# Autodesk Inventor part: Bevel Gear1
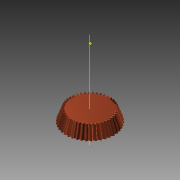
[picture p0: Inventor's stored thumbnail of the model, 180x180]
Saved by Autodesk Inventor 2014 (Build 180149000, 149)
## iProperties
Created: 2008-07
Part Number: Bevel Gear1
Material: Steel, Mild
Document SubType Name: Modeling
Designer: tangg
Categories: <?xml version="1.0" encoding="UTF-16"?> <MemberInstance><Categories><FamilyTemplate><FamilyTemplateParameter ValueType="xs:double" Id="1" ObjectReferenceKey="da
Mass: 60.9118 g
Surface Area: 34.3074 cm^2
Volume: 7.7496 cm^3
Density: 7.86 g/cm^3
Appearance: Copper - Polished
CustomPartVersion: 1
Author: tangg
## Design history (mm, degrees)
node "Top Point"
node "Mesh Plane2"
sketch "Teeth Body Sketch"
  geometry: L1 (0, 0)-(13.905, -43.186); L2 (13.905, -43.186)-(15.362, -42.687); L3 (15.362, -42.687)-(0, 0); L4 (14.7, -42.914)-(0, 0); L5 (11.453, -35.569)-(12.653, -35.158); L6 (13.905, -43.186)-(11.453, -35.569); L7 (15.362, -42.687)-(12.653, -35.158); L8 (0, -51.823)-(0, 8.637) reference; L9 (0, -42.914)-(15.362, -42.914)
  constraints: 16 end point, 4 point on line, 3 perpendicular, 2 collinear, 1 horizontal alignment, 1 vertical alignment
  dimensions: "d0" = 29.4 diameter of L4.start L8 (= da_de); "d1" = 27.81066 diameter of L1.end L8 (= da_dfe); "d2" = 30.72445 diameter of L2.end L8 (= da_dae); "d3" = 8 distance between parallel lines of L2 L5 (= da_b); "d4" = 42.68672 vertical distance of L2.end L1.start (= da_ve)
revolve "Teeth Body" sketch "Teeth Body Sketch" stored, may be unused: angle "d5" = 90 deg
node "Start Point"
node "Tooth Plane"
sketch "Start Sketch"
  geometry: L1 (0, -35.958)-(0, 11.125) reference; L2 (-0.217, -0.185)-(0.217, -0.185); A1 r 5.975 centre (-6.038, -1.531) between (-0.217, -0.185) and (-1.189, 1.96); A2 r 5.975 centre (6.038, -1.531) between (1.189, 1.96) and (0.217, -0.185); A3 r 16.701 centre (0, -14.699) between (1.189, 1.96) and (-1.189, 1.96); 1 further point
  constraints: 6 point on circle, 3 centre point, 3 symmetric about line, 2 end point, 1 coincident, 1 perpendicular, 1 other
  dimensions: "d7" = 5.97468 radius of A1 (= fd_rr); "d8" = 6.03788 horizontal distance of point (0, -14.699) A1.centre (= fd_x); "d9" = 13.16739 vertical distance of point (0, -14.699) A1.centre (= fd_y); "d57" = 16.70053 radius of A3 (= 0.5 x fd_dva + 0.3 x da_he); "d58" = 14.51373 distance from line of A3.centre L2 (= 0.5 x fd_dva - 1.12 x da_he)
node "End Point"
  node "End Plane"
sketch "3D Sketch Right"
  node "Helical Curve Right" dims "d65" = 286.15708 (computed from da_dm, da_delta, da_beta), "d66" = 31.5, "d67" = 29.4 (= da_de), "d68" = -3.30022 (= -da_delta), "d69" = 7.64113 (computed from fd_loft, da_delta)
node "End Plane Right"
sketch "End Sketch Right"
  geometry: L1 (0, -17.689)-(0, 5.893) reference; L2 (-0.178, -0.828)-(0.178, -0.828); A1 r 4.917 centre (-4.969, -1.936) between (-0.178, -0.828) and (-0.978, 0.937); A2 r 4.917 centre (4.969, -1.936) between (0.978, 0.937) and (0.178, -0.828); A3 r 13.744 centre (0, -12.772) between (0.978, 0.937) and (-0.978, 0.937); 1 further point
  constraints: 6 point on circle, 3 centre point, 3 symmetric about line, 2 end point, 1 coincident, 1 perpendicular, 1 other
  dimensions: "d70" = 4.96882 horizontal distance of A3.centre A1.centre (computed from fd_x, fd_ratio); "d71" = 10.83599 vertical distance of point (0, -12.772) A1.centre (computed from fd_y, fd_ratio); "d72" = 4.91681 radius of A1 (computed from fd_rr, fd_ratio); "d73" = 11.94395 distance from line of point (0, -12.772) L2 (computed from d58, fd_ratio); "d74" = 13.74356 radius of A3 (computed from d57, fd_ratio)
feature "Loft Right" sketch "End Sketch Right" dims "d75" = 0, "d76" = 90 deg, "d77" = 0, "d78" = 90 deg, "d79" = 0, "d80" = 90 deg, "d85" = 20, "da_teethtype" = 0 [user parameter]
sketch "3D Sketch Left"
  node "Helical Curve Left" dims "d26" = 286.15708 (computed from da_dm, da_delta, da_beta), "d27" = 7.64113 (computed from fd_loft, da_delta), "d28" = 29.4 (= da_de), "d29" = -3.30022 (= -da_delta)
node "End Plane Left"
sketch "End Sketch Left" dims "d56" = 11.97023 (derived)
  geometry: L1 (0, -33.711)-(0, 11.326) reference; L2 (-0.178, -0.827)-(0.178, -0.827); A1 r 4.917 centre (-4.969, -1.935) between (-0.178, -0.827) and (-0.978, 0.938); A2 r 4.917 centre (4.969, -1.935) between (0.978, 0.938) and (0.178, -0.827); A3 r 13.744 centre (0, -12.771) between (0.978, 0.938) and (-0.978, 0.938); 2 further points; 1 other entity
  constraints: 6 point on circle, 3 centre point, 3 symmetric about line, 2 end point, 1 coincident, 2 other
  dimensions: "d30" = 4.91681 radius of A1 (computed from fd_rr, fd_ratio); "d31" = 4.96882 horizontal distance of point (0, -12.771) A1.centre (computed from fd_x, fd_ratio); "d32" = 10.83599 vertical distance of A1.centre point (0, -12.771) (computed from fd_y, fd_ratio); "d61" = 13.74356 radius of A3 (computed from d57, fd_ratio); "d62" = 11.94395 distance from line of point (0, -12.771) L2 (computed from d58, fd_ratio)
feature "Loft Left" sketch "End Sketch Left" dims "d35" = 0, "d37" = 0, "d39" = 0, "d40" = 90 deg, "d63" = 90 deg, "d64" = 90 deg, "d84" = 10, "da_teethtype" = 0 [user parameter]
sketch "Body Sketch"
  geometry: L1 (0, -44.709)-(0, -34.046) reference; L2 (13.905, -43.186)-(11.453, -35.569) reference; L3 (11.453, -35.569)-(0, -35.569); L4 (13.905, -43.186)-(0, -43.186)
  constraints: 4 end point, 2 perpendicular, 2 point on line
revolve "Fix Body" sketch "Body Sketch" stored, may be unused: angle "d46" = 90 deg
sketch "Sketch6"
  geometry: L1 (14.7, -42.914)-(0, 0) reference; L2 (0, -51.496)-(0, 8.583) reference
feature "Pitch Diameter" sketch "Sketch6" dims angle "d47" = 90 deg
body "Solid1"
feature "Loft" dims "d17" = 0, "d18" = 90 deg, "d19" = 0, "d20" = 90 deg, "d89" = 0, "da_teethtype" = 0 [user parameter]
pattern_circular "Circular Pattern" dims angle "d22" = 360 deg, "d88" = 0, "da_teethtype" = 0 [user parameter]
pattern_circular "Circular Pattern Right" dims angle "d82" = 360 deg, "da_teethtype" = 0 [user parameter]
pattern_circular "Circular Pattern Left" dims angle "d42" = 360 deg, "da_teethtype" = 0 [user parameter]
sketch "End Sketch"
  geometry: L1 (0, -34.035)-(0, 10.392) reference; L2 (-0.178, 0.012)-(0.178, 0.012); A1 r 4.917 centre (-4.969, -1.096) between (-0.178, 0.012) and (-0.978, 1.777); A2 r 4.917 centre (4.969, -1.096) between (0.978, 1.777) and (0.178, 0.012); A3 r 13.744 centre (0, -11.932) between (0.978, 1.777) and (-0.978, 1.777); 1 further point
  constraints: 6 point on circle, 3 centre point, 3 symmetric about line, 2 end point, 1 coincident, 1 other
  dimensions: "d12" = 4.91681 radius of A1 (computed from fd_rr, fd_ratio); "d15" = 4.96882 horizontal distance of A1.centre point (0, -11.932) (computed from fd_x, fd_ratio); "d16" = 10.83599 vertical distance of A1.centre point (0, -11.932) (computed from fd_y, fd_ratio); "d59" = 13.74356 radius of A3 (computed from d57, fd_ratio); "d60" = 11.94395 distance from line of A3.centre L2 (computed from d58, fd_ratio)
body "Srf1"
other parameters: "da_b" = 8 [user parameter; used in 2 equation terms], "da_de" = 29.4 [user parameter; used in 4 equation terms], "da_dae" = 30.72445 [user parameter; used in 2 equation terms], "da_dfe" = 27.81066 [user parameter; used in 1 equation term], "da_le" = 45.36148 [user parameter; used in 1 equation term], "da_omega" = 45 deg [user parameter], "da_beta" = 0 [user parameter; used in 2 equation terms], "da_delta" = 3.30022 [user parameter; used in 8 equation terms], "da_alpha" = 20 deg [user parameter; used in 1 equation term], "da_he" = 1.54 [user parameter; used in 4 equation terms], "da_ve" = 42.68672 [user parameter; used in 1 equation term], "fd_dv" = 31.07706 (computed from da_de, da_delta) [user parameter; used in 1 equation term], "fd_dva" = 32.47706 (computed from da_dae, da_delta) [user parameter; used in 3 equation terms], "fd_dvb" = 29.20289 (computed from fd_dv, da_alpha) [user parameter; used in 2 equation terms], "da_zv" = 443.95805 [user parameter; used in 1 equation term], "fd_loft" = 8.077 (= da_b + 0.05 x da_he) [user parameter; used in 4 equation terms], "fd_ratio" = 8.22941 (computed from da_le, fd_loft) [user parameter; used in 15 equation terms], "fd_rr" = 5.97468 (computed from fd_dd, fd_dvb) [user parameter; used in 6 equation terms], "fd_angle" = 0.35382 (computed from da_zv) [user parameter; used in 4 equation terms], "fd_x1" = 0.54966 (computed from da_dvw, fd_angle) [user parameter; used in 1 equation term], "fd_y1" = 15.52881 (computed from da_dvw, fd_angle) [user parameter; used in 1 equation term], "fd_x2" = 5.48821 (computed from fd_rr, fd_angle2, fd_angle) [user parameter; used in 1 equation term], "fd_y2" = 2.36142 (computed from fd_rr, fd_angle2, fd_angle) [user parameter; used in 1 equation term], "fd_x" = 6.03788 (= fd_x1 + fd_x2) [user parameter; used in 4 equation terms], "fd_y" = 13.16739 (= fd_y1 - fd_y2) [user parameter; used in 4 equation terms], "fd_angle2" = 3.70945 (computed from fd_dvb, fd_dd) [user parameter; used in 2 equation terms], "fd_dd" = 31.55306 (= fd_dva - 0.6 x da_he) [user parameter; used in 2 equation terms], "da_dvw" = 31.07706 [user parameter; used in 2 equation terms], "d11" = -8.077 (= -fd_loft), "da_dm" = 26.80749 [user parameter; used in 2 equation terms], "da_x" = 0 [user parameter], "da_m" = 0.7 [user parameter], "d51" = 0.748 (computed from da_z)
